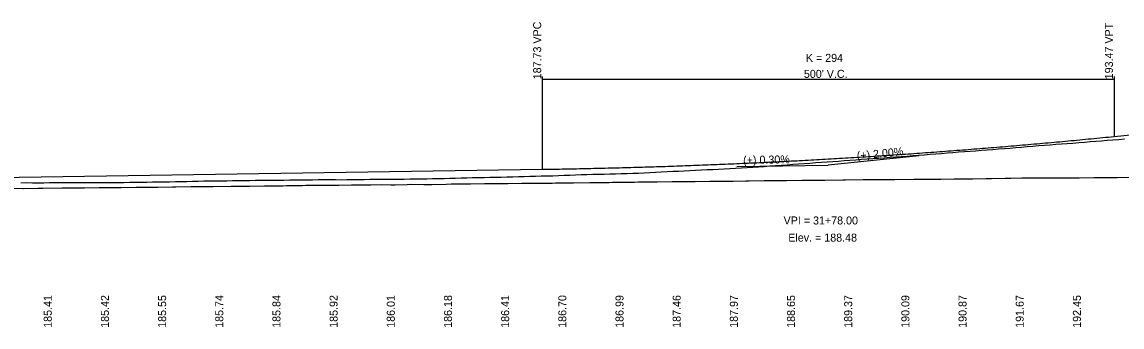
# Model space of a CAD drawing. Extents: x 1838386 to 1955906, y 719739 to 834437.
# Drawn here: x 1879136 to 1880098, y 820601 to 820868 of the extents above; entities that cross this region are included whole.
import ezdxf

# ---------------------------------------------------------------- set-up
doc = ezdxf.new("R2010")
doc.units = 0
for name, color, linetype in [('RD_DDB_GradeTX', 7, 'Continuous'), ('RD_DDB_Profile_EX', 7, 'Continuous'), ('RD_DDB_Profile_Lbl', 7, 'Continuous'), ('RD_DDB_Profile_PR', 7, 'Continuous'), ('RD_DDB_StripGrade', 7, 'Continuous'), ('RD_DDB_VCLbl', 7, 'Continuous'), ('RD_Sketch1', 7, 'Continuous')]:
    doc.layers.add(name, color=color, linetype=linetype)

msp = doc.modelspace()

# ---------------------------------------------------------------- linework, layer by layer
at = {"layer": 'RD_DDB_GradeTX'}
for p in [(1879920.69, 820750.48), (1879761.09, 820741.33)]:
    msp.add_line(p, (1879841.08, 820742.52), dxfattribs=at)
at = {"layer": 'RD_DDB_Profile_EX'}
for points in [[(1879890.15, 820748.94), (1879895.15, 820749.28), (1879900.15, 820749.64), (1879905.15, 820749.98), (1879910.15, 820750.33), (1879915.15, 820750.72), (1879920.15, 820751.09), (1879925.15, 820751.5), (1879930.15, 820751.91), (1879935.15, 820752.3), (1879940.15, 820752.71), (1879945.15, 820753.14), (1879950.15, 820753.54), (1879955.15, 820753.92), (1879960.15, 820754.28), (1879965.15, 820754.63), (1879970.15, 820755.01), (1879975.15, 820755.41), (1879980.15, 820755.8), (1879985.15, 820756.2), (1879990.15, 820756.61), (1879995.15, 820757.01), (1880000.15, 820757.38), (1880005.15, 820757.79), (1880010.15, 820758.21), (1880015.15, 820758.67), (1880020.15, 820759.09), (1880025.15, 820759.48), (1880030.15, 820759.91), (1880035.15, 820760.32), (1880040.15, 820760.72), (1880045.15, 820761.15), (1880050.15, 820761.33), (1880055.15, 820761.77), (1880060.15, 820762.15), (1880065.15, 820762.55), (1880070.15, 820763.01), (1880075.15, 820763.36), (1880080.15, 820763.73), (1880085.15, 820764.13), (1880090.15, 820764.53), (1880095.15, 820764.97), (1880100.15, 820765.39)], [(1879390.15, 820729.69), (1879395.15, 820729.77), (1879400.15, 820729.79), (1879405.15, 820729.75), (1879410.15, 820729.72), (1879415.15, 820729.69), (1879420.15, 820729.75), (1879425.15, 820729.82), (1879430.15, 820729.87), (1879435.15, 820729.93), (1879440.15, 820730), (1879445.15, 820730.07), (1879450.15, 820730.09), (1879455.15, 820730.12), (1879460.15, 820730.14), (1879465.15, 820730.21), (1879470.15, 820730.27), (1879475.15, 820730.33), (1879480.15, 820730.43), (1879485.15, 820730.48), (1879490.15, 820730.54), (1879495.15, 820730.61), (1879500.15, 820730.74), (1879505.15, 820730.85), (1879510.15, 820730.97), (1879515.15, 820731.1), (1879520.15, 820731.21), (1879525.15, 820731.32), (1879530.15, 820731.46), (1879535.15, 820731.63), (1879540.15, 820731.74), (1879545.15, 820731.83), (1879550.15, 820731.93), (1879555.15, 820732.01), (1879560.15, 820732.1), (1879565.15, 820732.25), (1879570.15, 820732.41), (1879575.15, 820732.56), (1879580.15, 820732.73), (1879585.15, 820732.88), (1879590.15, 820732.97), (1879595.15, 820733.06), (1879600.15, 820733.18), (1879605.15, 820733.36), (1879610.15, 820733.54), (1879615.15, 820733.72), (1879620.15, 820733.91), (1879625.15, 820734.09), (1879630.15, 820734.25), (1879635.15, 820734.42), (1879640.15, 820734.52), (1879645.15, 820734.59), (1879650.15, 820734.68), (1879655.15, 820734.84), (1879660.15, 820735), (1879665.15, 820735.16), (1879670.15, 820735.33), (1879675.15, 820735.53), (1879680.15, 820735.75), (1879685.15, 820736.01), (1879690.15, 820736.34), (1879695.15, 820736.64), (1879700.15, 820736.85), (1879705.15, 820737.06), (1879710.15, 820737.27), (1879715.15, 820737.5), (1879720.15, 820737.74), (1879725.15, 820737.99), (1879730.15, 820738.24), (1879735.15, 820738.49), (1879740.15, 820738.74), (1879745.15, 820738.98), (1879750.15, 820739.3), (1879755.15, 820739.59), (1879760.15, 820739.83), (1879765.15, 820740.09), (1879770.15, 820740.34), (1879775.15, 820740.62), (1879780.15, 820740.98), (1879785.15, 820741.34), (1879790.15, 820741.71), (1879795.15, 820742.01), (1879800.15, 820742.34), (1879805.15, 820742.74), (1879810.15, 820743.18), (1879815.15, 820743.52), (1879820.15, 820743.88), (1879825.15, 820744.25), (1879830.15, 820744.62), (1879835.15, 820744.95), (1879840.15, 820745.29), (1879845.15, 820745.66), (1879850.15, 820746.03), (1879855.15, 820746.4), (1879860.15, 820746.76), (1879865.15, 820747.17), (1879870.15, 820747.58), (1879875.15, 820747.9), (1879880.15, 820748.23), (1879885.15, 820748.6), (1879890.15, 820748.94)], [(1879135.15, 820727.04), (1879140.15, 820727.09), (1879145.15, 820727.07), (1879150.15, 820727.05), (1879155.15, 820727.07), (1879160.15, 820727.15), (1879165.15, 820727.16), (1879170.15, 820727.17), (1879175.15, 820727.2), (1879180.15, 820727.18), (1879185.15, 820727.13), (1879190.15, 820727.17), (1879195.15, 820727.19), (1879200.15, 820727.17), (1879205.15, 820727.19), (1879210.15, 820727.22), (1879215.15, 820727.25), (1879220.15, 820727.3), (1879225.15, 820727.37), (1879230.15, 820727.42), (1879235.15, 820727.47), (1879240.15, 820727.51), (1879245.15, 820727.58), (1879250.15, 820727.68), (1879255.15, 820727.75), (1879260.15, 820727.83), (1879265.15, 820727.93), (1879270.15, 820728.01), (1879275.15, 820728.1), (1879280.15, 820728.23), (1879285.15, 820728.37), (1879290.15, 820728.47), (1879295.15, 820728.59), (1879300.15, 820728.72), (1879305.15, 820728.82), (1879310.15, 820728.82), (1879315.15, 820728.83), (1879320.15, 820728.85), (1879325.15, 820728.98), (1879330.15, 820729.09), (1879335.15, 820729.12), (1879340.15, 820729.14), (1879345.15, 820729.16), (1879350.15, 820729.19), (1879355.15, 820729.25), (1879360.15, 820729.31), (1879365.15, 820729.37), (1879370.15, 820729.43), (1879375.15, 820729.49), (1879380.15, 820729.55), (1879385.15, 820729.61), (1879390.15, 820729.69)]]:
    msp.add_lwpolyline(points, dxfattribs=at)
at = {"layer": 'RD_DDB_Profile_PR'}
for p, q in [((1880091.08, 820767.49), (1880878.08, 820846.1)), ((1878390.15, 820720.78), (1879591.08, 820738.78))]:
    msp.add_line(p, q, dxfattribs=at)
msp.add_spline([(1879591.08, 820738.78), (1879601.08, 820738.94), (1879611.08, 820739.11), (1879621.08, 820739.3), (1879631.08, 820739.51), (1879641.08, 820739.74), (1879651.08, 820739.98), (1879661.08, 820740.24), (1879671.08, 820740.52), (1879681.08, 820740.81), (1879691.08, 820741.13), (1879701.08, 820741.45), (1879711.08, 820741.8), (1879721.08, 820742.16), (1879731.08, 820742.54), (1879741.08, 820742.94), (1879751.08, 820743.35), (1879761.08, 820743.78), (1879771.08, 820744.23), (1879781.08, 820744.69), (1879791.08, 820745.17), (1879801.08, 820745.67), (1879811.08, 820746.18), (1879821.08, 820746.72), (1879831.08, 820747.26), (1879841.08, 820747.83), (1879851.08, 820748.41), (1879861.08, 820749.01), (1879871.08, 820749.63), (1879881.08, 820750.26), (1879891.08, 820750.91), (1879901.08, 820751.58), (1879911.08, 820752.27), (1879921.08, 820752.97), (1879931.08, 820753.69), (1879941.08, 820754.42), (1879951.08, 820755.18), (1879961.08, 820755.94), (1879971.08, 820756.73), (1879981.08, 820757.53), (1879991.08, 820758.36), (1880001.08, 820759.19), (1880011.08, 820760.05), (1880021.08, 820760.92), (1880031.08, 820761.81), (1880041.08, 820762.71), (1880051.08, 820763.63), (1880061.08, 820764.57), (1880071.08, 820765.53), (1880081.08, 820766.5), (1880091.08, 820767.49)], degree=3, dxfattribs=at)
at = {"layer": 'RD_DDB_VCLbl'}
for p, q in [((1879591.08, 820819.99), (1879591.08, 820738.78)), ((1879591.08, 820817.49), (1880091.08, 820817.49)), ((1880091.08, 820819.99), (1880091.08, 820767.49))]:
    msp.add_line(p, q, dxfattribs=at)
at = {"layer": 'RD_Sketch1'}
msp.add_lwpolyline([(1879123.72, 820722.24), (1879136.67, 820722.1), (1879137.39, 820722.1), (1879150.19, 820722.3), (1879152.3, 820722.32), (1879154.31, 820722.33), (1879171.17, 820722.54), (1879174.18, 820722.57), (1879187.33, 820722.62), (1879190.7, 820722.65), (1879203.49, 820722.8), (1879206.91, 820722.86), (1879219.78, 820722.98), (1879222.78, 820722.98), (1879235.79, 820723.15), (1879238.99, 820723.19), (1879251.84, 820723.26), (1879254.81, 820723.29), (1879267.79, 820723.47), (1879270.67, 820723.49), (1879283.93, 820723.6), (1879287, 820723.62), (1879300.13, 820723.72), (1879303.29, 820723.74), (1879318.91, 820723.9), (1879320.41, 820723.94), (1879331.54, 820724.04), (1879334.93, 820724.11), (1879348.04, 820724.26), (1879351.64, 820724.28), (1879364.25, 820724.43), (1879367.5, 820724.47), (1879381.24, 820724.74), (1879384.19, 820724.76), (1879394.59, 820724.8), (1879397.61, 820724.82), (1879410.04, 820724.98), (1879413, 820725.02), (1879424.18, 820725.11), (1879427.55, 820725.15), (1879437.64, 820725.28), (1879441.16, 820725.31), (1879450.86, 820725.42), (1879458.52, 820725.27), (1879462.29, 820725.31), (1879472.86, 820725.62), (1879476.15, 820725.64), (1879487.53, 820725.56), (1879489.85, 820725.52), (1879494.59, 820725.58), (1879507.03, 820725.8), (1879511.29, 820725.92), (1879523.73, 820726.17), (1879528.18, 820726.19), (1879540.58, 820726.28), (1879544.48, 820726.33), (1879556.67, 820726.45), (1879560.78, 820726.47), (1879573.19, 820726.57), (1879583.03, 820726.65), (1879586.47, 820726.67), (1879599.63, 820726.78), (1879602.75, 820726.81), (1879615.71, 820727), (1879618.47, 820727.04), (1879632.51, 820727.18), (1879635.22, 820727.18), (1879649.56, 820727.33), (1879652.53, 820727.38), (1879659.19, 820727.53), (1879671.64, 820727.62), (1879674.99, 820727.7), (1879687.65, 820727.85), (1879691.61, 820727.92), (1879704.7, 820728.07), (1879708.04, 820728.11), (1879721.56, 820728.18), (1879724.74, 820728.2), (1879737.45, 820728.37), (1879741.09, 820728.38), (1879753.71, 820728.47), (1879757.96, 820728.5), (1879768.96, 820728.6), (1879771.99, 820728.65), (1879785.13, 820728.86), (1879787.64, 820728.89), (1879802.19, 820729.03), (1879804.69, 820729.04), (1879818.08, 820729.16), (1879821.03, 820729.18), (1879835.75, 820729.28), (1879838.27, 820729.31), (1879853.76, 820729.46), (1879854.86, 820729.46), (1879856.29, 820729.48), (1879871.78, 820729.72), (1879873.49, 820729.73), (1879888.4, 820729.77), (1879890.32, 820729.78), (1879899.41, 820729.8), (1879916.11, 820730.05), (1879918.71, 820730.06), (1879921.22, 820730.09), (1879935.38, 820730.18), (1879939.48, 820730.21), (1879951.26, 820730.33), (1879962.74, 820730.48), (1879967.42, 820730.54), (1879979.22, 820730.67), (1879983.93, 820730.73), (1879995.8, 820730.98), (1880000.76, 820731.07), (1880010.57, 820731.2), (1880015.23, 820731.27), (1880026.29, 820731.34), (1880029.44, 820731.34), (1880038.09, 820731.37), (1880046.57, 820731.37), (1880059.37, 820731.32), (1880060.5, 820731.35), (1880073.75, 820731.48), (1880077.23, 820731.54), (1880090.45, 820731.71), (1880093.9, 820731.71), (1880106.12, 820731.85)], dxfattribs=at)
msp.add_lwpolyline([(1879123.72, 820722.24), (1879136.67, 820722.1), (1879137.39, 820722.1), (1879150.19, 820722.3), (1879152.3, 820722.32), (1879154.31, 820722.33), (1879171.17, 820722.54), (1879174.18, 820722.57), (1879187.33, 820722.62), (1879190.7, 820722.65), (1879203.49, 820722.8), (1879206.91, 820722.86), (1879219.78, 820722.98), (1879222.78, 820722.98), (1879235.79, 820723.15), (1879238.99, 820723.19), (1879251.84, 820723.26), (1879254.81, 820723.29), (1879267.79, 820723.47), (1879270.67, 820723.49), (1879283.93, 820723.6), (1879287, 820723.62), (1879300.13, 820723.72), (1879303.29, 820723.74), (1879318.91, 820723.9), (1879320.41, 820723.94), (1879331.54, 820724.04), (1879334.93, 820724.11), (1879348.04, 820724.26), (1879351.64, 820724.28), (1879364.25, 820724.43), (1879367.5, 820724.47), (1879381.24, 820724.74), (1879384.19, 820724.76), (1879394.59, 820724.8), (1879397.61, 820724.82), (1879410.04, 820724.98), (1879413, 820725.02), (1879424.18, 820725.11), (1879427.55, 820725.15), (1879437.64, 820725.28), (1879441.16, 820725.31), (1879450.86, 820725.42), (1879458.52, 820725.27), (1879462.29, 820725.31), (1879472.86, 820725.62), (1879476.15, 820725.64), (1879487.53, 820725.56), (1879489.85, 820725.52), (1879494.59, 820725.58), (1879507.03, 820725.8), (1879511.29, 820725.92), (1879523.73, 820726.17), (1879528.18, 820726.19), (1879540.58, 820726.28), (1879544.48, 820726.33), (1879556.67, 820726.45), (1879560.78, 820726.47), (1879573.19, 820726.57), (1879583.03, 820726.65), (1879586.47, 820726.67), (1879599.63, 820726.78), (1879602.75, 820726.81), (1879615.71, 820727), (1879618.47, 820727.04), (1879632.51, 820727.18), (1879635.22, 820727.18), (1879649.56, 820727.33), (1879652.53, 820727.38), (1879659.19, 820727.53), (1879671.64, 820727.62), (1879674.99, 820727.7), (1879687.65, 820727.85), (1879691.61, 820727.92), (1879704.7, 820728.07), (1879708.04, 820728.11), (1879721.56, 820728.18), (1879724.74, 820728.2), (1879737.45, 820728.37), (1879741.09, 820728.38), (1879753.71, 820728.47), (1879757.96, 820728.5), (1879768.96, 820728.6), (1879771.99, 820728.65), (1879785.13, 820728.86), (1879787.64, 820728.89), (1879802.19, 820729.03), (1879804.69, 820729.04), (1879818.08, 820729.16), (1879821.03, 820729.18), (1879835.75, 820729.28), (1879838.27, 820729.31), (1879853.76, 820729.46), (1879854.86, 820729.46), (1879856.29, 820729.48), (1879871.78, 820729.72), (1879873.49, 820729.73), (1879888.4, 820729.77), (1879890.32, 820729.78), (1879899.41, 820729.8), (1879916.11, 820730.05), (1879918.71, 820730.06), (1879921.22, 820730.09), (1879935.38, 820730.18), (1879939.48, 820730.21), (1879951.26, 820730.33), (1879962.74, 820730.48), (1879967.42, 820730.54), (1879979.22, 820730.67), (1879983.93, 820730.73), (1879995.8, 820730.98), (1880000.76, 820731.07), (1880010.57, 820731.2), (1880015.23, 820731.27), (1880026.29, 820731.34), (1880029.44, 820731.34), (1880038.09, 820731.37), (1880046.57, 820731.37), (1880059.37, 820731.32), (1880060.5, 820731.35), (1880073.75, 820731.48), (1880077.23, 820731.54), (1880090.45, 820731.71), (1880093.9, 820731.71), (1880106.12, 820731.85)], dxfattribs=at)
msp.add_lwpolyline([(1879123.72, 820722.24), (1879136.67, 820722.1), (1879137.39, 820722.1), (1879150.19, 820722.3), (1879152.3, 820722.32), (1879154.31, 820722.33), (1879171.17, 820722.54), (1879174.18, 820722.57), (1879187.33, 820722.62), (1879190.7, 820722.65), (1879203.49, 820722.8), (1879206.91, 820722.86), (1879219.78, 820722.98), (1879222.78, 820722.98), (1879235.79, 820723.15), (1879238.99, 820723.19), (1879251.84, 820723.26), (1879254.81, 820723.29), (1879267.79, 820723.47), (1879270.67, 820723.49), (1879283.93, 820723.6), (1879287, 820723.62), (1879300.13, 820723.72), (1879303.29, 820723.74), (1879318.91, 820723.9), (1879320.41, 820723.94), (1879331.54, 820724.04), (1879334.93, 820724.11), (1879348.04, 820724.26), (1879351.64, 820724.28), (1879364.25, 820724.43), (1879367.5, 820724.47), (1879381.24, 820724.74), (1879384.19, 820724.76), (1879394.59, 820724.8), (1879397.61, 820724.82), (1879410.04, 820724.98), (1879413, 820725.02), (1879424.18, 820725.11), (1879427.55, 820725.15), (1879437.64, 820725.28), (1879441.16, 820725.31), (1879450.86, 820725.42), (1879458.52, 820725.27), (1879462.29, 820725.31), (1879472.86, 820725.62), (1879476.15, 820725.64), (1879487.53, 820725.56), (1879489.85, 820725.52), (1879494.59, 820725.58), (1879507.03, 820725.8), (1879511.29, 820725.92), (1879523.73, 820726.17), (1879528.18, 820726.19), (1879540.58, 820726.28), (1879544.48, 820726.33), (1879556.67, 820726.45), (1879560.78, 820726.47), (1879573.19, 820726.57), (1879583.03, 820726.65), (1879586.47, 820726.67), (1879599.63, 820726.78), (1879602.75, 820726.81), (1879615.71, 820727), (1879618.47, 820727.04), (1879632.51, 820727.18), (1879635.22, 820727.18), (1879649.56, 820727.33), (1879652.53, 820727.38), (1879659.19, 820727.53), (1879671.64, 820727.62), (1879674.99, 820727.7), (1879687.65, 820727.85), (1879691.61, 820727.92), (1879704.7, 820728.07), (1879708.04, 820728.11), (1879721.56, 820728.18), (1879724.74, 820728.2), (1879737.45, 820728.37), (1879741.09, 820728.38), (1879753.71, 820728.47), (1879757.96, 820728.5), (1879768.96, 820728.6), (1879771.99, 820728.65), (1879785.13, 820728.86), (1879787.64, 820728.89), (1879802.19, 820729.03), (1879804.69, 820729.04), (1879818.08, 820729.16), (1879821.03, 820729.18), (1879835.75, 820729.28), (1879838.27, 820729.31), (1879853.76, 820729.46), (1879854.86, 820729.46), (1879856.29, 820729.48), (1879871.78, 820729.72), (1879873.49, 820729.73), (1879888.4, 820729.77), (1879890.32, 820729.78), (1879899.41, 820729.8), (1879916.11, 820730.05), (1879918.71, 820730.06), (1879921.22, 820730.09), (1879935.38, 820730.18), (1879939.48, 820730.21), (1879951.26, 820730.33), (1879962.74, 820730.48), (1879967.42, 820730.54), (1879979.22, 820730.67), (1879983.93, 820730.73), (1879995.8, 820730.98), (1880000.76, 820731.07), (1880010.57, 820731.2), (1880015.23, 820731.27), (1880026.29, 820731.34), (1880029.44, 820731.34), (1880038.09, 820731.37), (1880046.57, 820731.37), (1880059.37, 820731.32), (1880060.5, 820731.35), (1880073.75, 820731.48), (1880077.23, 820731.54), (1880090.45, 820731.71), (1880093.9, 820731.71), (1880106.12, 820731.85)], dxfattribs=at)

# ---------------------------------------------------------------- texts
at = {"layer": 'RD_DDB_GradeTX'}
for s, rotation, p in [('(+) 2.00%', 5.70361, (1879866.43, 820747.07)), ('(+) 0.30%', 0.85858, (1879766.73, 820743.41))]:
    msp.add_text(s, height=7, rotation=rotation, dxfattribs=at).set_placement(p)
at = {"layer": 'RD_DDB_Profile_Lbl'}
for s, p in [('VPI = 31+78.00', (1879802.06, 820690.52)), ('Elev. = 188.48', (1879806.19, 820675.52))]:
    msp.add_text(s, height=7, dxfattribs=at).set_placement(p)
at = {"layer": 'RD_DDB_StripGrade'}
for s, p in [('187.73 VPC', (1879590.08, 820817.49)), ('193.47 VPT', (1880090.08, 820817.49)), ('185.41', (1879162.08, 820600.13)), ('185.42', (1879212.08, 820600.13)), ('185.55', (1879262.08, 820600.13)), ('185.74', (1879312.08, 820600.13)), ('185.84', (1879362.08, 820600.13)), ('185.92', (1879412.08, 820600.13)), ('186.01', (1879462.08, 820600.13)), ('186.18', (1879512.08, 820600.13)), ('186.41', (1879562.08, 820600.13)), ('186.70', (1879612.08, 820600.13)), ('186.99', (1879662.08, 820600.13)), ('187.46', (1879712.08, 820600.13)), ('187.97', (1879762.08, 820600.13)), ('188.65', (1879812.08, 820600.13)), ('189.37', (1879862.08, 820600.13)), ('190.09', (1879912.08, 820600.13)), ('190.87', (1879962.08, 820600.13)), ('191.67', (1880012.08, 820600.13)), ('192.45', (1880062.08, 820600.13))]:
    msp.add_text(s, height=7, rotation=90, dxfattribs=at).set_placement(p)
at = {"layer": 'RD_DDB_VCLbl'}
for s, p in [('K = 294', (1879821.56, 820832.74)), ("500' V.C.", (1879819.83, 820818.74))]:
    msp.add_text(s, height=7, dxfattribs=at).set_placement(p)

doc.saveas('drawing.dxf')
